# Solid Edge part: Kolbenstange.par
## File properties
Username: bmolnar
Dokumentum tartalom típus: 0
Author: bmolnar
Last saved by: bmolnar
Revision: 85
Sűrűség: 0,000 kg/m^3
Pontosság: 0,990
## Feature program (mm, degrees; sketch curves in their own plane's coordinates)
base feature "unnamed BaseFeature 1"
sketch for "unnamed Protrusion 1" #1 plane through (21, 0.0012, 0) normal (1, 0, 0) x-axis (0, 1, 0)
  circle centre (-0.0012, 0) radius 3.2
sketch for "unnamed Protrusion 1" #2 plane through (21, 0.0012, 0) normal (1, 0, 0) x-axis (0, 1, 0)
  circle centre (-0.0012, 0) radius 8
extrude "unnamed Protrusion 1" add finite 11.1 along -normal
sketch for "Kihúzás_3" plane through (21, 0.0012, 0) normal (1, 0, 0) x-axis (0, 1, 0)
  circle centre (-0.0012, 0) radius 8
extrude "Kihúzás_3" add finite 4.5 along +normal
sketch for "Furat_1" plane through (-36, 0, 0.0012) normal (-1, 0, 0) x-axis (0, 0, -1)
  hole centre (0.0012, 0) bore radius 1.621
hole "Furat_1" nominal diameter 4 finite  ThreadDepth = 9 mm; StartChamferOffset = 0.3 mm; StartChamferAngle = 45 deg; VBottomAngle = 118 deg
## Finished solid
Body 1: solid body, 18 faces, 24 edges, 8 vertices.
  Faces by surface: plane 8, cylinder 5, cone 3, torus 2
  Edges by curve: circle 14, line 6, curve on surface 2, ellipse 2
Bounding box of the edges (mm; curved faces can reach further): 63.500 x 16.000 x 16.000, from (-38, -8, -8) to (25.5, 8, 8).
Cylindrical faces by radius (mm): R1.621 x2, R2.125 x1, R4 x1, R8 x1
Conical faces (half-angle, radius in mm at the cone's reference point): 45 deg R1.921 x1, 45 deg R2.225 x1, 59 deg R1.621 x1
Toroidal faces (ring radius, tube radius in mm): R1.925 r0.2 x1, R2.7 r1.3 x1
Planar faces by outward normal: +x 1, +z 1, -x 3, -z 1, oblique 2
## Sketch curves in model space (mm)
circle centre (21, 0, 0) radius 8
circle centre (21, 0, 0) radius 3.2
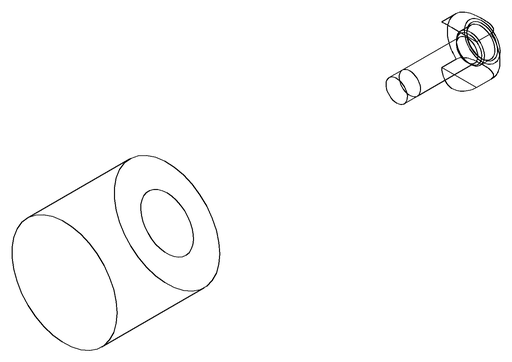
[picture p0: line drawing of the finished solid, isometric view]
